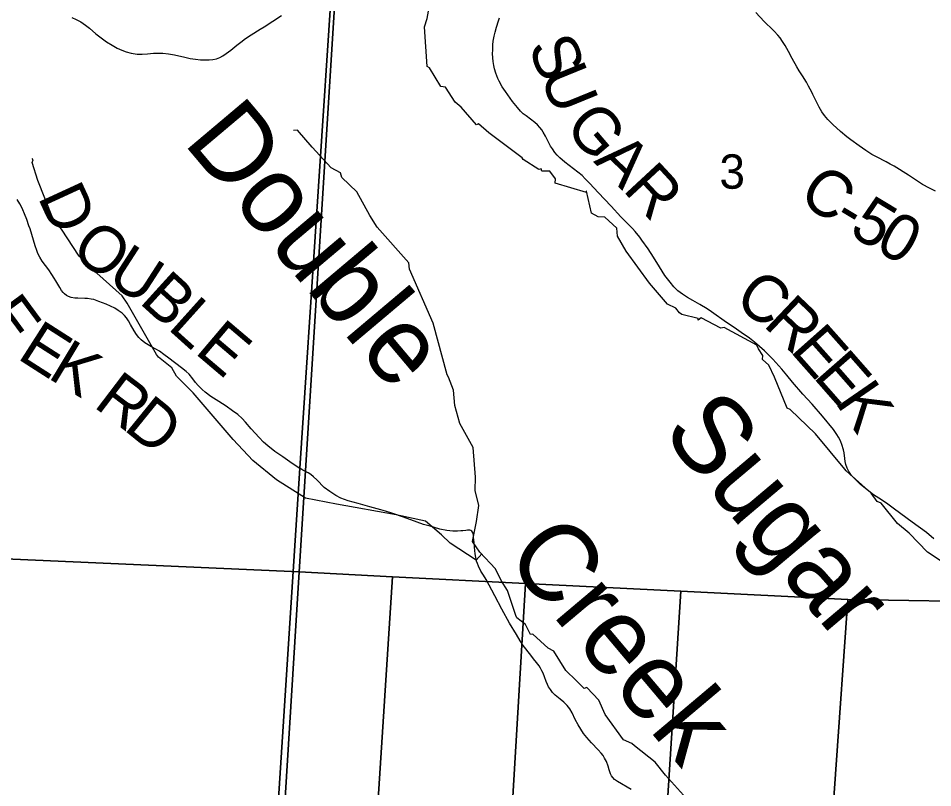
# Model space of a CAD drawing. Extents: x -2.1 to 31.9, y 6.3 to 28.3.
# Drawn here: x 4.032 to 5.147, y 21.508 to 22.446 of the extents above; entities that cross this region are included whole.
import ezdxf

# ---------------------------------------------------------------- set-up
doc = ezdxf.new("R2010")
doc.units = 0
for name, color, linetype in [('Default', 7, 'Continuous'), ('GM_X_County_Road', 7, 'Continuous'), ('GM_X_County_Road_Text', 7, 'Continuous'), ('GM_X_Minor_River', 7, 'Continuous'), ('GM_X_Minor_River_Text', 7, 'Continuous'), ('GM_X_Section', 7, 'Continuous'), ('GM_X_Section_Text', 7, 'Continuous'), ('GM_X_Township_Road', 7, 'Continuous'), ('GM_X_Township_Road_Text', 7, 'Continuous')]:
    doc.layers.add(name, color=color, linetype=linetype)

msp = doc.modelspace()

# ---------------------------------------------------------------- linework, layer by layer
at = {"layer": 'Default'}
msp.add_lwpolyline([(0.0344, 26.1105), (0.0344, 20.444), (3.7533, 20.444), (3.8489, 20.5389), (3.9894, 20.6326), (4.16, 20.7203), (4.2895, 20.7662), (4.3023, 20.7658), (4.3091, 20.8714), (4.3751, 21.8979), (4.4168, 22.5238), (4.4383, 22.8067), (4.4651, 23.2405), (4.4901, 23.6442), (4.5473, 24.5954), (4.5667, 24.9084), (4.6032, 25.4816), (4.6286, 25.8765), (3.8625, 25.9158), (3.0763, 25.9555), (2.8034, 25.9683), (2.0757, 26.0047), (0.4641, 26.0883)], close=True, dxfattribs=at)
msp.add_lwpolyline([(4.4901, 23.6442), (4.4651, 23.2405), (4.4383, 22.8067), (4.4168, 22.5238), (4.3751, 21.8979), (4.3091, 20.8714), (4.3023, 20.7658), (4.3525, 20.764), (4.3916, 20.7347), (4.4406, 20.7955), (4.5025, 20.8232), (4.6795, 20.8531), (4.9328, 20.8577), (5.1211, 20.8684), (5.1462, 20.8673), (5.351, 20.8306)], dxfattribs=at)
at = {"layer": 'GM_X_County_Road'}
for points in [[(4.0974, 22.447), (4.1027, 22.4447), (4.1081, 22.4418), (4.1138, 22.438), (4.1187, 22.4343), (4.1266, 22.4273), (4.1329, 22.4223), (4.1396, 22.4176), (4.1464, 22.4133), (4.1525, 22.41), (4.1582, 22.4074), (4.1634, 22.4055), (4.1694, 22.4037), (4.1768, 22.4025), (4.1831, 22.4024), (4.1893, 22.4029), (4.1967, 22.4036), (4.1991, 22.4036), (4.2028, 22.4038), (4.2083, 22.4036), (4.215, 22.4028), (4.2223, 22.4016), (4.235, 22.3987), (4.2417, 22.3973), (4.2479, 22.3963), (4.2541, 22.3957), (4.2597, 22.3954), (4.2647, 22.3955), (4.2691, 22.396), (4.2734, 22.3969), (4.2775, 22.3984), (4.2814, 22.4004), (4.2855, 22.4033), (4.2909, 22.4075), (4.2982, 22.4134), (4.3031, 22.4172), (4.3091, 22.4215), (4.3157, 22.4261), (4.3268, 22.433), (4.3315, 22.4359), (4.353, 22.4496)], [(5.1502, 22.2356), (5.1426, 22.2392), (5.1342, 22.2438), (5.1169, 22.2549), (5.0996, 22.2658), (5.0948, 22.2686), (5.0897, 22.2713), (5.0779, 22.2774), (5.0724, 22.2804), (5.0651, 22.2851), (5.0569, 22.2908), (5.047, 22.2981), (5.0421, 22.3018), (5.0343, 22.3082), (5.0248, 22.3169), (5.0186, 22.3229), (5.0147, 22.3278), (5.0115, 22.3323), (5.0084, 22.3378), (5.0006, 22.3533), (4.9991, 22.3562), (4.9953, 22.3636), (4.9926, 22.3683), (4.9878, 22.3759), (4.9838, 22.3821), (4.9809, 22.3871), (4.9753, 22.3972), (4.9707, 22.4059), (4.9668, 22.4131), (4.9637, 22.4181), (4.9605, 22.4226), (4.958, 22.4256), (4.9534, 22.4306), (4.9501, 22.4337), (4.9432, 22.4404), (4.941, 22.4425), (4.9308, 22.4534)], [(5.1479, 21.8119), (5.1389, 21.8196), (5.1215, 21.8321), (5.0999, 21.848), (5.0919, 21.8538), (5.0841, 21.8591), (5.0743, 21.8655), (5.0684, 21.8701), (5.0587, 21.8781), (5.0517, 21.8847), (5.0476, 21.8891), (5.0443, 21.8938), (5.0422, 21.8979), (5.0408, 21.9024), (5.04, 21.9058), (5.0394, 21.9095), (5.0385, 21.9165), (5.0378, 21.9202), (5.036, 21.9268), (5.0348, 21.9299), (5.0334, 21.9329), (5.0318, 21.9356), (5.0298, 21.939), (5.0257, 21.945), (5.0123, 21.9611), (4.9995, 21.9758), (4.9883, 21.9882), (4.9757, 22.0026), (4.9686, 22.0112), (4.9625, 22.0184), (4.9589, 22.0226), (4.9516, 22.0308), (4.9452, 22.0371), (4.9415, 22.0407), (4.9354, 22.0462), (4.9293, 22.0515), (4.9234, 22.0564), (4.9131, 22.0634), (4.9046, 22.0692), (4.8952, 22.0755), (4.8771, 22.0884), (4.8715, 22.0922), (4.8629, 22.0973), (4.8544, 22.1022), (4.8477, 22.1061), (4.8416, 22.1098), (4.8361, 22.1139), (4.8309, 22.1189), (4.8264, 22.1244), (4.8201, 22.1329), (4.8134, 22.1432), (4.8061, 22.1551), (4.7996, 22.1651), (4.7922, 22.1758), (4.7896, 22.1793), (4.784, 22.1862), (4.7807, 22.1898), (4.7665, 22.2044), (4.7545, 22.2171), (4.7388, 22.234), (4.7288, 22.245), (4.7231, 22.2507), (4.7192, 22.2546), (4.7141, 22.2588), (4.6983, 22.2709), (4.6922, 22.2761), (4.689, 22.2792), (4.6862, 22.2826), (4.683, 22.2871), (4.6809, 22.2902), (4.679, 22.2938), (4.6766, 22.2983), (4.6745, 22.3026), (4.6719, 22.3073), (4.6702, 22.3101), (4.6679, 22.3133), (4.6649, 22.3163), (4.6616, 22.3191), (4.651, 22.3272), (4.6476, 22.3299), (4.6442, 22.3332), (4.6405, 22.3374), (4.6344, 22.3447), (4.626, 22.3568), (4.6218, 22.3628), (4.6181, 22.3695), (4.6164, 22.373), (4.614, 22.3793), (4.6125, 22.3846), (4.6116, 22.3886), (4.6109, 22.3935), (4.6102, 22.4027), (4.6103, 22.4077), (4.6105, 22.414), (4.611, 22.4184), (4.6122, 22.4244), (4.6133, 22.4295), (4.6149, 22.4353), (4.6172, 22.443), (4.6184, 22.4468)]]:
    msp.add_lwpolyline(points, dxfattribs=at)
at = {"layer": 'GM_X_Minor_River'}
for points in [[(4.6866, 22.2454), (4.6869, 22.2507), (4.6801, 22.2598), (4.6703, 22.2598), (4.6692, 22.2628), (4.6665, 22.2621), (4.6476, 22.2742), (4.6461, 22.2761), (4.6056, 22.3068), (4.5931, 22.3174), (4.5905, 22.3162), (4.5719, 22.3379), (4.5644, 22.3439), (4.5526, 22.3621), (4.547, 22.3629), (4.5333, 22.386), (4.5303, 22.3876), (4.5273, 22.4358), (4.5303, 22.4461), (4.5337, 22.4639)], [(4.8574, 21.483), (4.8207, 21.5236), (4.8082, 21.5396), (4.7832, 21.5596), (4.7798, 21.5623), (4.7696, 21.5668), (4.7473, 21.5976), (4.7397, 21.615), (4.7249, 21.6306), (4.7219, 21.6294), (4.7121, 21.6389), (4.6996, 21.6514), (4.6848, 21.6749), (4.678, 21.6783), (4.6591, 21.6954), (4.6564, 21.695), (4.6504, 21.7075), (4.6398, 21.7155), (4.6383, 21.7182), (4.6284, 21.7489), (4.6205, 21.7611), (4.6137, 21.7751), (4.5947, 21.7956), (4.5857, 21.8085), (4.5905, 21.8328), (4.5932, 21.8522), (4.589, 21.8708), (4.5894, 21.8868), (4.5863, 21.9229), (4.57, 21.9525), (4.564, 21.9741), (4.5624, 21.9928), (4.5564, 22.0087), (4.5549, 22.0117), (4.5378, 22.0748), (4.509, 22.1405), (4.5079, 22.1481), (4.4693, 22.1917), (4.4605, 22.2057), (4.4446, 22.2346), (4.4265, 22.252), (4.4246, 22.2577), (4.4132, 22.2638), (4.3902, 22.2892), (4.3724, 22.3097), (4.3675, 22.3096)], [(4.5969, 21.7933), (4.5902, 21.7857), (4.5584, 21.8065), (4.5478, 21.8168), (4.5282, 21.8334), (4.4926, 21.841), (4.42, 21.8541), (4.3822, 21.8612), (4.3467, 21.8836), (4.3179, 21.9071), (4.2941, 21.9329), (4.2453, 21.9898), (4.2248, 22.0102), (4.2192, 22.0201), (4.2029, 22.033), (4.2006, 22.0364), (4.1647, 22.099), (4.1586, 22.1081), (4.1276, 22.1354), (4.1185, 22.1411), (4.1155, 22.1483), (4.106, 22.1563), (4.0848, 22.1893), (4.0738, 22.2033), (4.056, 22.2485), (4.0488, 22.2705), (4.0503, 22.2736), (4.0488, 22.2755)], [(4.7248, 22.2337), (4.6866, 22.2454)], [(5.1569, 21.7847), (5.1402, 21.7953), (5.1179, 21.8188), (5.1035, 21.8306), (5.0838, 21.8552), (5.0789, 21.8571), (5.0717, 21.8674), (5.0411, 21.8947), (5.0396, 21.8966), (5.0036, 21.9398), (4.973, 21.9694), (4.9692, 21.9709), (4.9537, 22.0089), (4.9469, 22.0233), (4.9393, 22.0305), (4.9397, 22.0354), (4.9344, 22.0434), (4.9321, 22.0479), (4.8924, 22.0695), (4.8882, 22.0684), (4.8644, 22.0812), (4.8606, 22.0782), (4.8606, 22.0805), (4.841, 22.085), (4.8379, 22.0873), (4.8334, 22.0929), (4.8232, 22.0979), (4.8012, 22.1233), (4.7728, 22.1624), (4.7622, 22.1806), (4.7615, 22.1905), (4.7471, 22.2037), (4.7388, 22.2041), (4.7305, 22.2086), (4.7244, 22.2356), (4.724, 22.2357)]]:
    msp.add_lwpolyline(points, dxfattribs=at)
at = {"layer": 'GM_X_Section'}
for points in [[(4.4397, 22.818), (5.498, 22.7781), (5.4326, 21.7271), (5.2409, 21.7347), (5.043, 21.7379), (4.8395, 21.7479), (4.6504, 21.7575), (4.4881, 21.7655), (4.3744, 21.7716), (4.4255, 22.5906)], [(4.4255, 22.5906), (4.3744, 21.7716), (3.823, 21.7961), (3.8692, 22.6281)], [(4.4881, 21.7655), (4.6504, 21.7575), (4.5978, 20.8744), (4.5722, 20.8721), (4.5381, 20.869), (4.4721, 20.8602), (4.4513, 20.8563), (4.4415, 20.854), (4.4292, 20.8518)], [(4.6504, 21.7575), (4.8395, 21.7479), (4.7851, 20.8904), (4.7684, 20.8896), (4.746, 20.8888), (4.7278, 20.888), (4.718, 20.8865), (4.7085, 20.8838), (4.6945, 20.8819), (4.6873, 20.8807), (4.6767, 20.8803), (4.6502, 20.8787), (4.6294, 20.8772), (4.6021, 20.8748), (4.5978, 20.8744)], [(4.8395, 21.7479), (5.043, 21.7379), (4.9832, 20.8861), (4.9605, 20.8885), (4.9438, 20.89), (4.9313, 20.8911), (4.9245, 20.8911), (4.9071, 20.8918), (4.8892, 20.8921), (4.8665, 20.8924), (4.8495, 20.8932), (4.8328, 20.8924), (4.8089, 20.8916), (4.7915, 20.8908), (4.7851, 20.8904)], [(5.043, 21.7379), (5.2409, 21.7347), (5.1841, 20.8829), (5.1718, 20.8832), (5.1324, 20.8853), (5.1275, 20.8861), (5.1249, 20.8854), (5.117, 20.8862), (5.0992, 20.8854), (5.0844, 20.8853), (5.0764, 20.8857), (5.0598, 20.8849), (5.0499, 20.8841), (5.031, 20.8833), (5.0143, 20.8829), (4.9961, 20.8848), (4.9832, 20.8861)]]:
    msp.add_lwpolyline(points, close=True, dxfattribs=at)
for points in [[(3.295, 21.1893), (3.3214, 21.6276), (3.333, 21.819), (3.823, 21.7961), (4.3744, 21.7716), (4.3154, 20.8197)], [(4.3154, 20.8197), (4.3744, 21.7716), (4.4881, 21.7655), (4.4292, 20.8518)]]:
    msp.add_lwpolyline(points, dxfattribs=at)
at = {"layer": 'GM_X_Township_Road'}
for points in [[(4.3762, 21.8969), (4.3753, 21.8974), (4.3657, 21.9035), (4.3545, 21.9115), (4.3449, 21.9183), (4.3362, 21.9249), (4.331, 21.9295), (4.3257, 21.9352), (4.3159, 21.9459), (4.3089, 21.9541), (4.3049, 21.9584), (4.2995, 21.9632), (4.2933, 21.9678), (4.2852, 21.9735), (4.2764, 21.9791), (4.2668, 21.9853), (4.2597, 21.9905), (4.256, 21.9937), (4.2514, 21.9985), (4.2481, 22.0023), (4.2448, 22.0067), (4.2404, 22.0124), (4.2368, 22.0159), (4.231, 22.0203), (4.2157, 22.032), (4.2096, 22.0366), (4.2043, 22.0404), (4.1996, 22.043), (4.1944, 22.0457), (4.1861, 22.0508), (4.1816, 22.0544), (4.1788, 22.0571), (4.1759, 22.0608), (4.1731, 22.0654), (4.1688, 22.0729), (4.1662, 22.0774), (4.1639, 22.081), (4.1614, 22.084), (4.1587, 22.0868), (4.1538, 22.0901), (4.1497, 22.0927), (4.139, 22.0977), (4.1303, 22.1012), (4.1241, 22.1033), (4.1209, 22.104), (4.1164, 22.1046), (4.1132, 22.1047), (4.1046, 22.1049), (4.1008, 22.1052), (4.0964, 22.106), (4.0934, 22.107), (4.0906, 22.1085), (4.0883, 22.1103), (4.0868, 22.112), (4.0848, 22.1146), (4.0828, 22.118), (4.0778, 22.1264), (4.0759, 22.1296), (4.073, 22.1339), (4.0692, 22.1396), (4.0613, 22.1503), (4.0584, 22.1549), (4.0559, 22.1595), (4.0544, 22.1633), (4.0527, 22.1687), (4.0506, 22.1758), (4.0484, 22.1828), (4.0463, 22.1894), (4.045, 22.1934), (4.0423, 22.2008), (4.0397, 22.2077), (4.0377, 22.2128), (4.036, 22.2164), (4.0339, 22.2201), (4.0305, 22.2254)], [(4.779, 21.5061), (4.7623, 21.5161), (4.7588, 21.5186), (4.7565, 21.5209), (4.7552, 21.523), (4.754, 21.5252), (4.7523, 21.5303), (4.7511, 21.5347), (4.7488, 21.5405), (4.7467, 21.5446), (4.7449, 21.5476), (4.7426, 21.5504), (4.7387, 21.5547), (4.7305, 21.5632), (4.7249, 21.5697), (4.721, 21.5744), (4.7175, 21.5796), (4.7143, 21.5852), (4.7106, 21.5917), (4.7071, 21.5996), (4.7042, 21.6044), (4.7009, 21.6084), (4.6968, 21.6126), (4.6924, 21.6165), (4.6865, 21.6212), (4.6833, 21.6245), (4.6806, 21.6279), (4.6784, 21.6314), (4.6769, 21.6343), (4.6756, 21.6377), (4.6734, 21.6435), (4.6717, 21.6481), (4.6703, 21.651), (4.6686, 21.654), (4.6668, 21.6568), (4.6635, 21.6612), (4.6601, 21.6655), (4.6578, 21.6684), (4.6506, 21.6778), (4.6476, 21.6819), (4.6438, 21.6874), (4.6392, 21.6951), (4.6309, 21.7089), (4.6214, 21.7261), (4.6128, 21.7424), (4.6024, 21.7622), (4.5991, 21.7676), (4.5959, 21.7724), (4.5928, 21.7784), (4.5916, 21.7817), (4.5907, 21.7844), (4.5897, 21.7889), (4.5889, 21.7934), (4.5881, 21.8015), (4.5877, 21.8072), (4.587, 21.8132), (4.5868, 21.8158), (4.5863, 21.8185), (4.5856, 21.82), (4.5848, 21.821), (4.5836, 21.8218), (4.5822, 21.8222), (4.581, 21.8223), (4.5796, 21.8222), (4.5777, 21.822), (4.574, 21.8216), (4.5716, 21.8213), (4.5673, 21.8211), (4.5648, 21.8211), (4.5617, 21.8212), (4.5542, 21.822), (4.546, 21.8237), (4.534, 21.827), (4.5261, 21.8293), (4.518, 21.8322), (4.5015, 21.8381), (4.4875, 21.8429), (4.4795, 21.8454), (4.474, 21.8472), (4.4606, 21.8509), (4.4461, 21.8547), (4.434, 21.8579), (4.4253, 21.8615), (4.4192, 21.8647), (4.4116, 21.8696), (4.4048, 21.8744), (4.3957, 21.8835), (4.3919, 21.8872), (4.3887, 21.8901), (4.3854, 21.892), (4.379, 21.8953), (4.3762, 21.8969)]]:
    msp.add_lwpolyline(points, dxfattribs=at)

# ---------------------------------------------------------------- texts
at = {"layer": 'GM_X_County_Road_Text'}
for s, rotation, p in [('S', 291.8041, (4.6528, 22.4125)), ('U', 292.1717, (4.6672, 22.3766)), ('G', 310.484, (4.6963, 22.3134)), ('A', 315.4554, (4.7324, 22.2714)), ('R', 312.8248, (4.7676, 22.2369)), ('C', 324.0746, (4.9807, 22.2262)), ('5', 328.8546, (5.0429, 22.1839)), ('-', 329.0458, (5.023, 22.1959)), ('0', 330.4203, (5.0743, 22.1649)), ('C', 324.0036, (4.9024, 22.0983)), ('R', 316.4353, (4.9387, 22.0722)), ('E', 311.5826, (4.9716, 22.0409)), ('E', 311.267, (4.9997, 22.0092)), ('K', 304.6035, (5.0267, 21.9786))]:
    msp.add_text(s, height=0.0568, rotation=rotation, dxfattribs=at).set_placement(p)
at = {"layer": 'GM_X_Minor_River_Text'}
for s, rotation, p in [('Double', 310.1353, (4.2318, 22.2951)), ('Sugar', 310.1349, (4.8148, 21.9409)), ('Creek', 310.135, (4.6231, 21.789))]:
    msp.add_text(s, height=0.09469, rotation=rotation, dxfattribs=at).set_placement(p)
at = {"layer": 'GM_X_Section_Text'}
msp.add_text('3', height=0.0419, rotation=0, dxfattribs=at).set_placement((4.8866, 22.2385))
at = {"layer": 'GM_X_Township_Road_Text'}
for s, rotation, p in [('D', 294.7141, (4.0552, 22.2285)), ('O', 321.3458, (4.0938, 22.1606)), ('U', 327.1464, (4.1379, 22.1257)), ('B', 317.7636, (4.178, 22.1001)), ('E', 306.3456, (3.9875, 22.082)), ('L', 318.0924, (4.2128, 22.0684)), ('E', 327.3764, (4.0292, 22.0323)), ('E', 319.7162, (4.2457, 22.0389)), ('K', 328.9222, (4.0664, 22.0085)), ('R', 322.7648, (4.1223, 21.9736)), ('D', 320.9272, (4.159, 21.9457))]:
    msp.add_text(s, height=0.0568, rotation=rotation, dxfattribs=at).set_placement(p)

doc.saveas('drawing.dxf')
